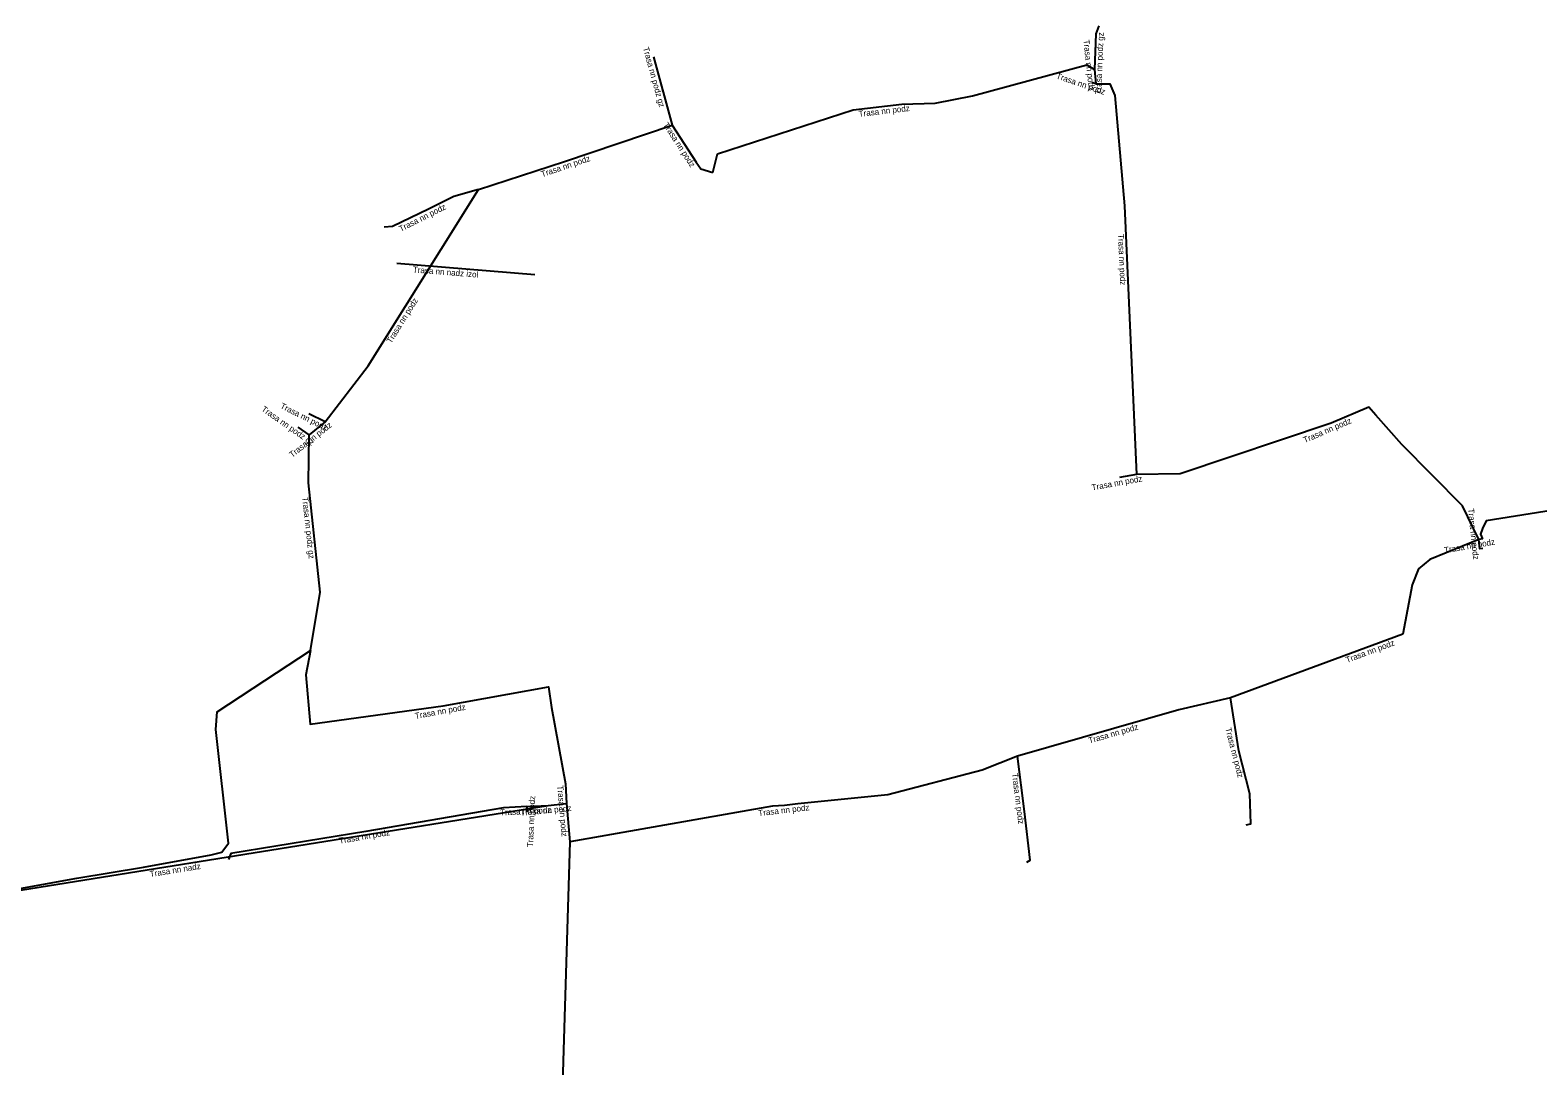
# Model space of a CAD drawing. Extents: x -682605 to -681812, y -1059958 to -1059650.
# Drawn here: x -682127.3 to -682001.8, y -1059800.1 to -1059713.9 of the extents above; entities that cross this region are included whole.
import ezdxf

# ---------------------------------------------------------------- set-up
doc = ezdxf.new("R2010")
doc.units = 0
doc.layers.add('Popiskový text - Ostatní atributy Trasy', color=7, linetype='Continuous')
doc.layers.add('Spojnice NN', color=7, linetype='Continuous')

msp = doc.modelspace()

# ---------------------------------------------------------------- linework, layer by layer
at = {"layer": 'Spojnice NN'}
for points in [[(-682038.37, -1059713.5), (-682038.63, -1059714.17), (-682038.75, -1059717.15)], [(-682075.45, -1059716.08), (-682073.88, -1059721.78)], [(-682070.52, -1059725.73), (-682070.13, -1059724.17), (-682058.84, -1059720.49), (-682054.79, -1059720.02), (-682052, -1059719.96), (-682048.89, -1059719.33), (-682039.37, -1059716.77), (-682038.75, -1059717.15)], [(-682038.75, -1059717.15), (-682038.62, -1059718.35)], [(-682038.62, -1059718.35), (-682038.97, -1059718.23)], [(-682038.62, -1059718.35), (-682037.46, -1059718.35), (-682037.04, -1059719.3), (-682036.25, -1059728.49), (-682035.24, -1059750.85)], [(-682090.02, -1059727.12), (-682082.85, -1059724.8), (-682073.88, -1059721.78)], [(-682073.88, -1059721.78), (-682071.89, -1059724.86), (-682071.52, -1059725.41), (-682070.52, -1059725.73)], [(-682102.77, -1059746.48), (-682099.19, -1059741.81), (-682090.02, -1059727.12)], [(-682090.02, -1059727.12), (-682092.06, -1059727.71), (-682094.18, -1059728.78), (-682097.18, -1059730.21), (-682097.86, -1059730.28)], [(-682096.81, -1059733.27), (-682085.31, -1059734.2)], [(-682102.77, -1059746.48), (-682104.13, -1059745.8)], [(-682006.74, -1059756.26), (-682008.1, -1059753.47), (-682013.17, -1059748.37), (-682015.33, -1059745.91), (-682015.92, -1059745.26), (-682019.04, -1059746.59), (-682031.61, -1059750.8), (-682035.24, -1059750.85)], [(-682104.12, -1059747.54), (-682105.02, -1059746.91)], [(-682104, -1059765.49), (-682103.18, -1059760.66), (-682104.17, -1059751.56), (-682104.12, -1059747.54)], [(-682102.77, -1059746.48), (-682104.12, -1059747.54)], [(-682035.24, -1059750.85), (-682036.66, -1059751.11)], [(-681973.04, -1059750.26), (-681976.75, -1059750.5), (-681993.23, -1059752.66), (-682006.15, -1059754.71), (-682006.44, -1059755.34), (-682006.62, -1059755.81), (-682006.45, -1059756.21)], [(-682006.74, -1059756.26), (-682010.82, -1059757.92), (-682011.77, -1059758.71), (-682012.3, -1059760.03), (-682013.09, -1059764.13), (-682027.43, -1059769.44)], [(-682006.45, -1059756.21), (-682006.74, -1059756.26)], [(-682006.42, -1059757), (-682006.66, -1059757.05), (-682006.74, -1059756.26)], [(-682129.42, -1059785.53), (-682123.44, -1059784.44), (-682117.89, -1059783.54), (-682112.27, -1059782.52), (-682111.38, -1059782.3), (-682110.81, -1059781.54), (-682111.88, -1059772.07), (-682111.76, -1059770.62), (-682106.83, -1059767.35), (-682104, -1059765.49)], [(-682104, -1059765.49), (-682104.38, -1059767.53), (-682104.01, -1059771.64), (-682092.96, -1059770.12), (-682084.2, -1059768.53), (-682083.93, -1059770.24), (-682082.78, -1059776.61), (-682082.68, -1059778.24)], [(-682027.43, -1059769.44), (-682031.72, -1059770.43), (-682045.14, -1059774.29)], [(-682026.11, -1059780.01), (-682025.72, -1059779.93), (-682025.8, -1059777.43), (-682026.72, -1059773.84), (-682027.43, -1059769.44)], [(-682045.14, -1059774.29), (-682048.09, -1059775.45), (-682055.93, -1059777.51), (-682063.42, -1059778.26), (-682064.54, -1059778.39), (-682065.53, -1059778.47), (-682082.4, -1059781.44)], [(-682044.37, -1059783.11), (-682044.09, -1059782.95), (-682044.56, -1059778.91), (-682045.14, -1059774.29)], [(-682144.43, -1059788.05), (-682084.21, -1059778.39)], [(-682085.98, -1059778.48), (-682087.94, -1059778.6), (-682099.39, -1059780.56), (-682110.62, -1059782.39), (-682110.81, -1059782.91)], [(-682085.98, -1059778.48), (-682086, -1059778.93)], [(-682085.98, -1059778.48), (-682084.21, -1059778.39)], [(-682084.21, -1059778.39), (-682082.68, -1059778.24)], [(-682082.68, -1059778.24), (-682082.4, -1059781.44)], [(-682082.4, -1059781.44), (-682082.96, -1059799.69), (-682083.41, -1059815.33), (-682084.2, -1059822.7), (-682084.78, -1059823.76)]]:
    msp.add_lwpolyline(points, dxfattribs=at)

# ---------------------------------------------------------------- texts
at = {"layer": 'Popiskový text - Ostatní atributy Trasy'}
for s, rotation, p in [('Trasa nn podz', 276.1829, (-682039.67, -1059714.69)), ('Trasa nn podz gz', 87.7486, (-682038.18, -1059719.22)), ('Trasa nn podz gz', 285.3996, (-682076.33, -1059715.35)), ('Trasa nn podz', 341.0754, (-682041.98, -1059717.88)), ('Trasa nn podz', 6.6195, (-682058.34, -1059721.09)), ('Trasa nn podz', 302.8667, (-682074.67, -1059721.75)), ('Trasa nn podz', 18.6072, (-682084.71, -1059726.11)), ('Trasa nn podz', 26.8163, (-682096.48, -1059730.67)), ('Trasa nn podz', 272.5863, (-682036.79, -1059730.85)), ('Trasa nn nadz izol', 355.3642, (-682095.49, -1059734.03)), ('Trasa nn podz', 58.0262, (-682097.28, -1059739.98)), ('Trasa nn podz', 333.4349, (-682106.56, -1059745.31)), ('Trasa nn podz gz', 325.008, (-682108.13, -1059745.52)), ('Trasa nn podz', 23.0877, (-682021.24, -1059748.24)), ('Trasa nn podz', 38.1385, (-682105.52, -1059749.47)), ('Trasa nn podz', 10.3758, (-682038.93, -1059752.19)), ('Trasa nn podz gz', 276.2089, (-682104.69, -1059752.75)), ('Trasa nn podz', 275.7824, (-682007.65, -1059753.71)), ('Trasa nn podz', 9.7824, (-682009.59, -1059757.41)), ('Trasa nn podz', 20.3192, (-682017.72, -1059766.54)), ('Trasa nn podz', 10.2876, (-682095.26, -1059771.2)), ('Trasa nn podz', 16.0468, (-682039.16, -1059773.25)), ('Trasa nn podz', 284.3737, (-682027.86, -1059771.99)), ('Trasa nn podz', 277.1555, (-682045.61, -1059775.74)), ('Trasa nn podz', 87.4552, (-682085.48, -1059781.88)), ('Trasa nn podz', 275.0006, (-682083.46, -1059776.76)), ('Trasa nn podz', 2.9108, (-682088.21, -1059779.24)), ('Trasa nn podz', 5.5993, (-682086.51, -1059779.27)), ('Trasa nn podz', 6.6208, (-682066.69, -1059779.29)), ('Trasa nn podz', 9.7137, (-682101.57, -1059781.59)), ('Trasa nn nadz', 9.1133, (-682117.33, -1059784.36))]:
    msp.add_text(s, height=0.5, rotation=rotation, dxfattribs=at).set_placement(p)

doc.saveas('drawing.dxf')
